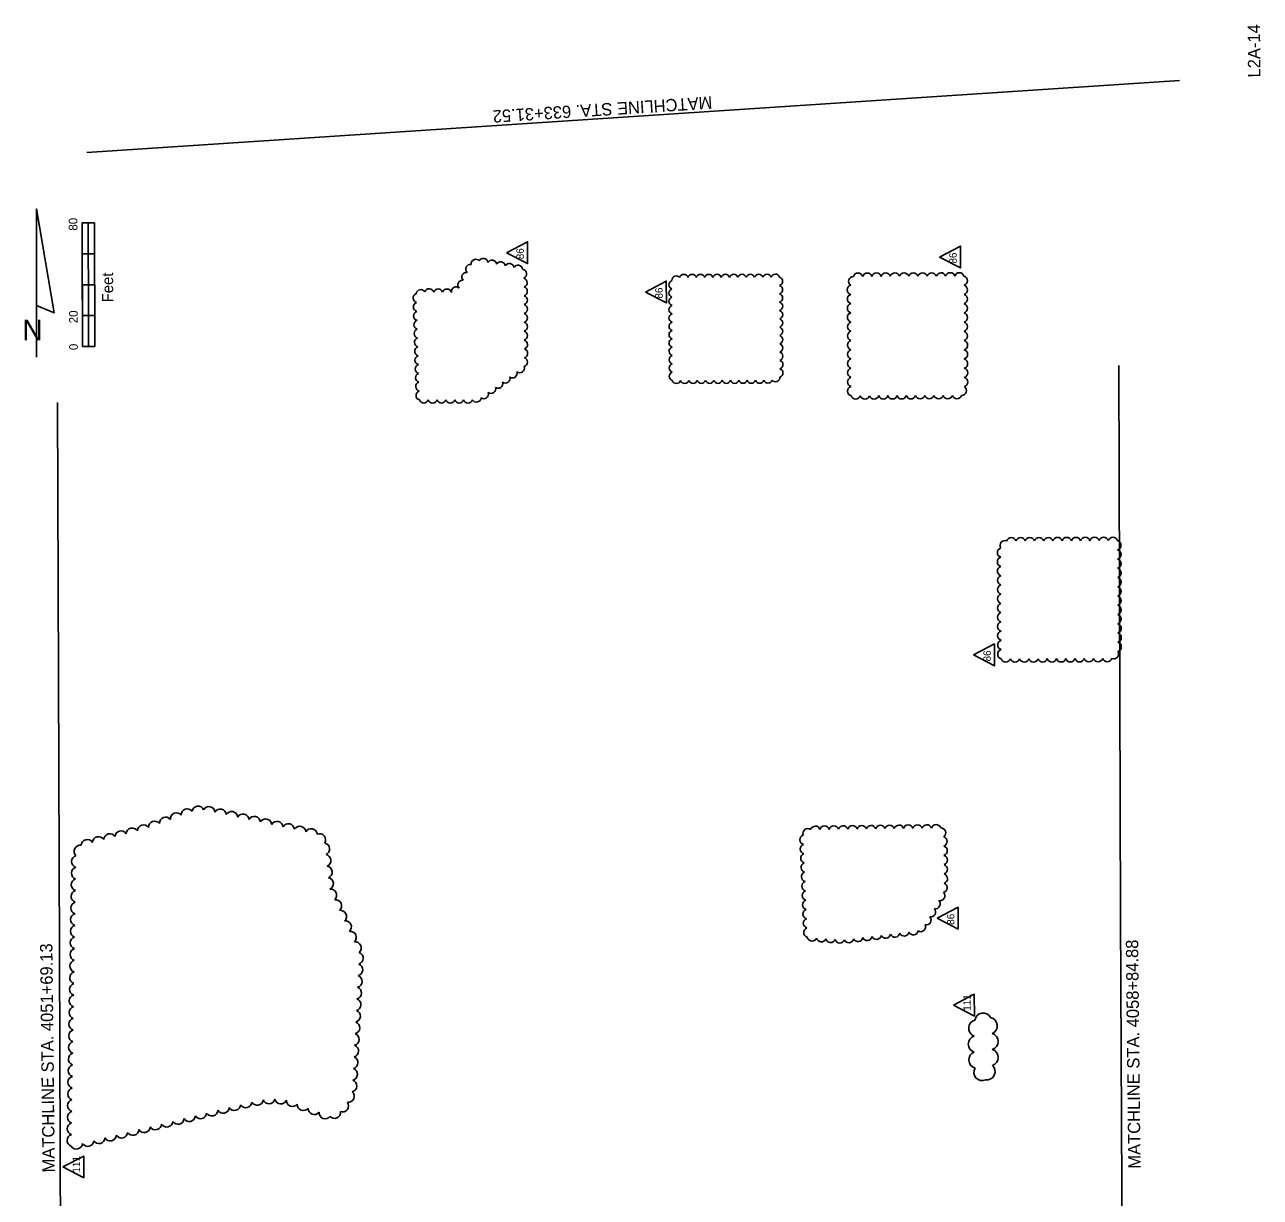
# Model space of a CAD drawing. Extents: x 928735 to 929560, y 637957 to 639219.
# Drawn here: x 928735 to 929535, y 638460 to 639219 of the extents above; entities that cross this region are included whole.
import ezdxf

# ---------------------------------------------------------------- set-up
doc = ezdxf.new("R2010")
doc.units = 0
for name, color, linetype in [('Cloud_dp', 7, 'Continuous'), ('MatchLines_dp', 7, 'Continuous'), ('NorthArw_dp', 7, 'Continuous'), ('Scale_dp', 7, 'Continuous'), ('TextShtNo', 7, 'Continuous')]:
    doc.layers.add(name, color=color, linetype=linetype)

msp = doc.modelspace()

# ---------------------------------------------------------------- linework, layer by layer
at = {"layer": 'Cloud_dp'}
for points in [[(929047.1, 639071.19), (929060.69, 639064.19), (929060.64, 639078.28)], [(929327.44, 639068.38), (929341.03, 639061.39), (929340.98, 639075.47)], [(929136.99, 639045.72), (929150.58, 639038.73), (929150.53, 639052.81)], [(929349.53, 638810.78), (929363.11, 638803.78), (929363.07, 638817.87)], [(929325.95, 638640.25), (929339.53, 638633.26), (929339.49, 638647.34)], [(929336.48, 638583.91), (929350.06, 638576.91), (929350.02, 638591)], [(928759.68, 638479.2), (928773.27, 638472.2), (928773.22, 638486.29)]]:
    msp.add_lwpolyline(points, close=True, dxfattribs=at)
for centre, radius, start, end in [((929027.13, 639063.94), 3.01, 41.87422, 186.87422), ((929032.01, 639064.5), 3.01, 6.44158, 151.44158), ((929037.63, 639063.4), 3.01, 6.44158, 151.44158), ((929043.26, 639062.31), 3.01, 6.44158, 151.44158), ((929021.11, 639055.48), 3.01, 80.96807, 225.96807), ((929023.67, 639060.61), 3.01, 80.96807, 225.96807), ((929048.88, 639061.21), 3.01, 6.44158, 151.44158), ((929054.51, 639060.11), 3, 6.44158, 151.44158), ((929057.03, 639057.47), 3.01, 296.04486, 81.04486), ((929161.87, 639054.29), 2.83, 17.69643, 162.69643), ((929167.26, 639054.31), 2.83, 17.69643, 162.69643), ((929172.66, 639054.33), 2.83, 17.69643, 162.69643), ((929178.05, 639054.35), 2.83, 17.69643, 162.69643), ((929183.44, 639054.37), 2.83, 17.69643, 162.69643), ((929188.83, 639054.39), 2.83, 17.69643, 162.69643), ((929194.22, 639054.4), 2.83, 17.69643, 162.69643), ((929199.61, 639054.42), 2.83, 17.69643, 162.69643), ((929205, 639054.44), 2.83, 17.69643, 162.69643), ((929210.39, 639054.46), 2.83, 17.69643, 162.69643), ((929215.78, 639054.48), 2.83, 17.69643, 162.69643), ((929221.17, 639054.5), 2.83, 17.69643, 162.69643), ((929274.73, 639054.9), 3.13, 17.69643, 162.69643), ((929280.69, 639054.92), 3.13, 17.69643, 162.69643), ((929286.66, 639054.94), 3.13, 17.69643, 162.69643), ((929292.62, 639054.96), 3.13, 17.69643, 162.69643), ((929298.59, 639054.98), 3.13, 17.69643, 162.69643), ((929304.55, 639055), 3.13, 17.69643, 162.69643), ((929310.52, 639055.02), 3.13, 17.69643, 162.69643), ((929316.48, 639055.04), 3.13, 17.69643, 162.69643), ((929322.44, 639055.06), 3.13, 17.69643, 162.69643), ((929328.41, 639055.08), 3.13, 17.69643, 162.69643), ((929334.37, 639055.1), 3.13, 17.69643, 162.69643), ((929340.34, 639055.12), 3.13, 17.69643, 162.69643), ((929014.35, 639046.05), 3.01, 45.32878, 190.32878), ((929018.55, 639050.35), 3.01, 80.96807, 225.96807), ((929057.46, 639051.9), 3.01, 287.80104, 72.80104), ((929057.49, 639046.17), 3.01, 287.80104, 72.80104), ((929155.03, 639050.45), 2.83, 107.69643, 252.69643), ((929156.99, 639053.35), 2.82, 39.1821, 184.1821), ((929223.03, 639052.66), 2.83, 287.69643, 72.69643), ((929223.04, 639047.27), 2.83, 287.69643, 72.69643), ((929270.89, 639047.17), 3.13, 107.69643, 252.69643), ((929271.73, 639052.7), 3.12, 89.88872, 234.88872), ((929342.39, 639053.09), 3.13, 287.69643, 72.69643), ((929342.41, 639047.12), 3.13, 287.69643, 72.69643), ((928989.57, 639041.78), 3.01, 109.1948, 254.1948), ((928991.58, 639044.31), 3, 29.17471, 174.17471), ((928997.05, 639044.83), 3.01, 16.63437, 161.63437), ((929002.78, 639044.74), 3.01, 16.63437, 161.63437), ((929008.51, 639044.65), 3.01, 16.63437, 161.63437), ((929057.52, 639040.44), 3.01, 287.80104, 72.80104), ((929155.05, 639045.06), 2.83, 107.69643, 252.69643), ((929155.07, 639039.67), 2.83, 107.69643, 252.69643), ((929223.06, 639041.88), 2.83, 287.69643, 72.69643), ((929270.91, 639041.2), 3.13, 107.69643, 252.69643), ((929342.43, 639041.16), 3.13, 287.69643, 72.69643), ((928989.74, 639036.05), 3.01, 109.1948, 254.1948), ((928989.91, 639030.32), 3.01, 109.1948, 254.1948), ((929057.55, 639034.7), 3.01, 287.80104, 72.80104), ((929155.08, 639034.28), 2.83, 107.69643, 252.69643), ((929223.08, 639036.49), 2.83, 287.69643, 72.69643), ((929223.1, 639031.09), 2.83, 287.69643, 72.69643), ((929270.93, 639035.24), 3.13, 107.69643, 252.69643), ((929342.45, 639035.19), 3.13, 287.69643, 72.69643), ((928990.08, 639024.59), 3.01, 109.1948, 254.1948), ((929057.58, 639028.97), 3.01, 287.80104, 72.80104), ((929057.61, 639023.24), 3.01, 287.80104, 72.80104), ((929155.1, 639028.89), 2.83, 107.69643, 252.69643), ((929155.12, 639023.5), 2.83, 107.69643, 252.69643), ((929223.12, 639025.7), 2.83, 287.69643, 72.69643), ((929270.95, 639029.27), 3.13, 107.69643, 252.69643), ((929270.97, 639023.31), 3.13, 107.69643, 252.69643), ((929342.47, 639029.23), 3.13, 287.69643, 72.69643), ((929342.49, 639023.26), 3.13, 287.69643, 72.69643), ((928990.25, 639018.86), 3.01, 109.1948, 254.1948), ((929057.64, 639017.51), 3.01, 287.80104, 72.80104), ((929155.14, 639018.11), 2.83, 107.69643, 252.69643), ((929223.14, 639020.31), 2.83, 287.69643, 72.69643), ((929223.15, 639014.92), 2.83, 287.69643, 72.69643), ((929270.99, 639017.34), 3.13, 107.69643, 252.69643), ((929342.51, 639017.3), 3.13, 287.69643, 72.69643), ((928990.42, 639013.13), 3.01, 109.1948, 254.1948), ((928990.59, 639007.4), 3.01, 109.1948, 254.1948), ((929057.67, 639011.77), 3.01, 287.80104, 72.80104), ((929057.7, 639006.04), 3.01, 287.80104, 72.80104), ((929155.16, 639012.72), 2.83, 107.69643, 252.69643), ((929155.18, 639007.32), 2.83, 107.69643, 252.69643), ((929223.17, 639009.53), 2.83, 287.69643, 72.69643), ((929271.01, 639011.38), 3.13, 107.69643, 252.69643), ((929342.53, 639011.33), 3.13, 287.69643, 72.69643), ((928990.76, 639001.67), 3.01, 109.1948, 254.1948), ((929057.63, 639000.34), 3.01, 285.75263, 70.75263), ((929155.2, 639001.93), 2.83, 107.69643, 252.69643), ((929223.19, 639004.14), 2.83, 287.69643, 72.69643), ((929223.21, 638998.75), 2.83, 287.69643, 72.69643), ((929271.03, 639005.41), 3.13, 107.69643, 252.69643), ((929271.05, 638999.45), 3.13, 107.69643, 252.69643), ((929342.55, 639005.37), 3.13, 287.69643, 72.69643), ((929342.57, 638999.4), 3.13, 287.69643, 72.69643), ((928990.93, 638995.94), 3.01, 109.1948, 254.1948), ((928991.1, 638990.21), 3.01, 109.1948, 254.1948), ((929050.95, 638993.13), 3.01, 233.44773, 18.44773), ((929055.59, 638996.5), 3, 233.44773, 18.44773), ((929155.21, 638996.54), 2.83, 107.69643, 252.69643), ((929155.23, 638991.15), 2.83, 107.69643, 252.69643), ((929223.23, 638993.36), 2.83, 287.69643, 72.69643), ((929271.07, 638993.49), 3.13, 107.69643, 252.69643), ((929342.59, 638993.44), 3.13, 287.69643, 72.69643), ((928991.27, 638984.48), 3.01, 109.1948, 254.1948), ((929041.67, 638986.4), 3.01, 233.44773, 18.44773), ((929046.31, 638989.77), 3.01, 233.44773, 18.44773), ((929157.08, 638989.31), 2.83, 197.69643, 342.69643), ((929162.48, 638989.33), 2.83, 197.69643, 342.69643), ((929167.87, 638989.35), 2.83, 197.69643, 342.69643), ((929173.26, 638989.37), 2.83, 197.69643, 342.69643), ((929178.65, 638989.39), 2.83, 197.69643, 342.69643), ((929184.04, 638989.41), 2.83, 197.69643, 342.69643), ((929189.43, 638989.42), 2.83, 197.69643, 342.69643), ((929194.82, 638989.44), 2.83, 197.69643, 342.69643), ((929200.21, 638989.46), 2.83, 197.69643, 342.69643), ((929205.6, 638989.48), 2.83, 197.69643, 342.69643), ((929210.99, 638989.5), 2.83, 197.69643, 342.69643), ((929216.38, 638989.52), 2.83, 197.69643, 342.69643), ((929221.27, 638990.46), 2.82, 219.1821, 4.1821), ((929271.09, 638987.52), 3.13, 107.69643, 252.69643), ((929271.11, 638981.56), 3.13, 107.69643, 252.69643), ((929342.61, 638987.47), 3.13, 287.69643, 72.69643), ((928991.44, 638978.75), 3.01, 109.1948, 254.1948), ((929027.6, 638977.5), 3.01, 210.44534, 355.44534), ((929032.39, 638979.67), 3.01, 233.44773, 18.44773), ((929037.03, 638983.04), 3.01, 233.44773, 18.44773), ((929273.16, 638979.52), 3.13, 197.69643, 342.69643), ((929279.13, 638979.54), 3.13, 197.69643, 342.69643), ((929285.09, 638979.56), 3.13, 197.69643, 342.69643), ((929291.06, 638979.58), 3.13, 197.69643, 342.69643), ((929297.02, 638979.6), 3.13, 197.69643, 342.69643), ((929302.99, 638979.62), 3.13, 197.69643, 342.69643), ((929308.95, 638979.64), 3.13, 197.69643, 342.69643), ((929314.92, 638979.66), 3.13, 197.69643, 342.69643), ((929320.88, 638979.68), 3.13, 197.69643, 342.69643), ((929326.85, 638979.7), 3.13, 197.69643, 342.69643), ((929332.81, 638979.72), 3.13, 197.69643, 342.69643), ((929338.78, 638979.75), 3.13, 197.69643, 342.69643), ((929341.77, 638981.94), 3.12, 269.88872, 54.88872), ((928993.48, 638976.77), 3.01, 197.69643, 342.69643), ((928999.22, 638976.79), 3.01, 197.69643, 342.69643), ((929004.95, 638976.81), 3.01, 197.69643, 342.69643), ((929010.68, 638976.83), 3.01, 197.69643, 342.69643), ((929016.41, 638976.85), 3.01, 197.69643, 342.69643), ((929022.14, 638976.87), 3.01, 197.69643, 342.69643), ((929369.78, 638881.66), 3.13, 66.77308, 211.77308), ((929374.01, 638883.61), 3.14, 17.69643, 162.69643), ((929379.99, 638883.63), 3.14, 17.69643, 162.69643), ((929385.97, 638883.65), 3.14, 17.69643, 162.69643), ((929391.95, 638883.67), 3.14, 17.69643, 162.69643), ((929397.93, 638883.69), 3.14, 17.69643, 162.69643), ((929403.91, 638883.71), 3.14, 17.69643, 162.69643), ((929409.9, 638883.73), 3.14, 17.69643, 162.69643), ((929415.88, 638883.75), 3.14, 17.69643, 162.69643), ((929421.86, 638883.77), 3.14, 17.69643, 162.69643), ((929427.84, 638883.79), 3.14, 17.69643, 162.69643), ((929433.82, 638883.81), 3.14, 17.69643, 162.69643), ((929439.8, 638883.83), 3.14, 17.69643, 162.69643), ((929441.85, 638881.79), 3.14, 287.69643, 72.69643), ((929368.07, 638877.02), 3.14, 107.69643, 252.69643), ((929368.09, 638871.04), 3.14, 107.69643, 252.69643), ((929441.87, 638875.81), 3.14, 287.69643, 72.69643), ((929441.89, 638869.83), 3.14, 287.69643, 72.69643), ((929368.11, 638865.06), 3.14, 107.69643, 252.69643), ((929441.92, 638863.85), 3.14, 287.69643, 72.69643), ((929368.13, 638859.08), 3.14, 107.69643, 252.69643), ((929441.94, 638857.87), 3.14, 287.69643, 72.69643), ((929368.15, 638853.1), 3.14, 107.69643, 252.69643), ((929368.17, 638847.12), 3.14, 107.69643, 252.69643), ((929441.96, 638851.89), 3.14, 287.69643, 72.69643), ((929441.98, 638845.91), 3.14, 287.69643, 72.69643), ((929368.19, 638841.14), 3.14, 107.69643, 252.69643), ((929442, 638839.93), 3.14, 287.69643, 72.69643), ((929368.21, 638835.16), 3.14, 107.69643, 252.69643), ((929442.02, 638833.95), 3.14, 287.69643, 72.69643), ((929368.23, 638829.18), 3.14, 107.69643, 252.69643), ((929368.26, 638823.2), 3.14, 107.69643, 252.69643), ((929442.04, 638827.97), 3.14, 287.69643, 72.69643), ((929442.06, 638821.99), 3.14, 287.69643, 72.69643), ((929368.28, 638817.22), 3.14, 107.69643, 252.69643), ((929442.08, 638816.01), 3.14, 287.69643, 72.69643), ((929368.3, 638811.24), 3.14, 107.69643, 252.69643), ((929436.14, 638809.42), 3.14, 197.69643, 342.69643), ((929440.37, 638811.37), 3.13, 246.77308, 31.77308), ((929370.35, 638809.2), 3.14, 197.69643, 342.69643), ((929376.33, 638809.22), 3.14, 197.69643, 342.69643), ((929382.31, 638809.24), 3.14, 197.69643, 342.69643), ((929388.29, 638809.26), 3.14, 197.69643, 342.69643), ((929394.27, 638809.28), 3.14, 197.69643, 342.69643), ((929400.25, 638809.3), 3.14, 197.69643, 342.69643), ((929406.24, 638809.32), 3.14, 197.69643, 342.69643), ((929412.22, 638809.34), 3.14, 197.69643, 342.69643), ((929418.2, 638809.36), 3.14, 197.69643, 342.69643), ((929424.18, 638809.38), 3.14, 197.69643, 342.69643), ((929430.16, 638809.4), 3.14, 197.69643, 342.69643), ((928847.29, 638708.9), 3.95, 24.77078, 169.77078), ((928854.3, 638708.6), 3.95, 5.31461, 150.31461), ((928826.23, 638701.84), 3.95, 38.20479, 183.20479), ((928833.27, 638704.5), 3.95, 38.20479, 183.20479), ((928840.31, 638707.16), 3.95, 38.20479, 183.20479), ((928861.66, 638707.01), 3.95, 5.31461, 150.31461), ((928869.01, 638705.42), 3.95, 5.31461, 150.31461), ((928876.37, 638703.83), 3.95, 5.31461, 150.31461), ((928883.72, 638702.24), 3.95, 5.31461, 150.31461), ((928891.08, 638700.65), 3.95, 5.31461, 150.31461), ((928797.4, 638692.87), 3.95, 31.87512, 176.87512), ((928804.69, 638694.73), 3.95, 31.87512, 176.87512), ((928811.98, 638696.75), 3.95, 33.99958, 178.99958), ((928819.19, 638699.18), 3.95, 38.20479, 183.20479), ((928898.44, 638699.07), 3.95, 5.31461, 150.31461), ((928905.79, 638697.48), 3.95, 5.31461, 150.31461), ((928913.15, 638695.89), 3.95, 5.31461, 150.31461), ((928920.5, 638694.3), 3.95, 5.31461, 150.31461), ((929242.15, 638695.13), 3.15, 53.92896, 198.92896), ((929247.02, 638696.77), 3.16, 18.19349, 163.19349), ((929253.04, 638696.84), 3.16, 18.19349, 163.19349), ((929259.06, 638696.91), 3.16, 18.19349, 163.19349), ((929265.08, 638696.98), 3.16, 18.19349, 163.19349), ((929271.1, 638697.06), 3.16, 18.19349, 163.19349), ((929277.12, 638697.13), 3.16, 18.19349, 163.19349), ((929283.13, 638697.2), 3.16, 18.19349, 163.19349), ((929289.15, 638697.28), 3.16, 18.19349, 163.19349), ((929295.17, 638697.35), 3.16, 18.19349, 163.19349), ((929301.19, 638697.42), 3.16, 18.19349, 163.19349), ((929307.21, 638697.49), 3.16, 18.19349, 163.19349), ((929313.23, 638697.57), 3.16, 18.19349, 163.19349), ((929319.24, 638697.64), 3.16, 18.19349, 163.19349), ((929325.26, 638697.71), 3.16, 18.19349, 163.19349), ((929328.35, 638695.55), 3.15, 306.63247, 91.63247), ((928775.53, 638687.26), 3.95, 31.87512, 176.87512), ((928782.82, 638689.13), 3.95, 31.87512, 176.87512), ((928790.11, 638691), 3.95, 31.87512, 176.87512), ((928925.98, 638691.04), 3.95, 328.17052, 113.17052), ((928928.57, 638685.09), 3.95, 293.74766, 78.74766), ((929240.23, 638691.14), 3.16, 109.81544, 254.81544), ((929329.31, 638690), 3.16, 288.01668, 73.01668), ((928769.33, 638676.97), 3.95, 106.56514, 251.56514), ((928770.95, 638683.58), 3.95, 80.7548, 225.7548), ((928929.38, 638677.61), 3.95, 293.74766, 78.74766), ((929240.47, 638685.12), 3.16, 109.81544, 254.81544), ((929240.72, 638679.11), 3.16, 109.81544, 254.81544), ((929329.37, 638683.98), 3.16, 288.01668, 73.01668), ((929329.42, 638677.96), 3.16, 288.01668, 73.01668), ((928769.2, 638669.45), 3.95, 106.56514, 251.56514), ((928930.2, 638670.13), 3.95, 293.74766, 78.74766), ((929240.96, 638673.09), 3.16, 109.81544, 254.81544), ((929329.47, 638671.94), 3.16, 288.01668, 73.01668), ((928769.08, 638661.93), 3.95, 106.56514, 251.56514), ((928931.02, 638662.65), 3.95, 293.74766, 78.74766), ((929241.2, 638667.08), 3.16, 109.81544, 254.81544), ((929329.53, 638665.92), 3.16, 288.01668, 73.01668), ((928768.96, 638654.4), 3.95, 106.56514, 251.56514), ((928933.11, 638655.12), 3.95, 312.21207, 97.21207), ((929241.45, 638661.07), 3.16, 109.81544, 254.81544), ((929241.69, 638655.05), 3.16, 109.81544, 254.81544), ((929327.76, 638654.77), 3.16, 257.91481, 42.91481), ((929329.34, 638659.99), 3.16, 283.34081, 68.34081), ((928768.84, 638646.88), 3.95, 106.56514, 251.56514), ((928936.28, 638648.29), 3.95, 312.56023, 97.56023), ((929241.93, 638649.04), 3.16, 109.81544, 254.81544), ((929324.79, 638649.54), 3.16, 257.91481, 42.91481), ((928768.71, 638639.35), 3.95, 106.56514, 251.56514), ((928939.46, 638641.47), 3.95, 312.56023, 97.56023), ((929242.18, 638643.02), 3.16, 109.81544, 254.81544), ((929318.84, 638639.07), 3.16, 257.91481, 42.91481), ((929321.81, 638644.3), 3.16, 257.91481, 42.91481), ((928768.59, 638631.83), 3.95, 106.56514, 251.56514), ((928942.65, 638634.66), 3.95, 312.56023, 97.56023), ((929242.42, 638637.01), 3.16, 109.81544, 254.81544), ((929242.66, 638631), 3.16, 109.81544, 254.81544), ((929315.29, 638634.71), 3.16, 238.69803, 23.69803), ((928768.47, 638624.31), 3.95, 106.56514, 251.56514), ((928945.84, 638627.84), 3.95, 312.56023, 97.56023), ((928949.03, 638621.02), 3.94, 312.56023, 97.56023), ((929244.91, 638628.65), 3.16, 192.7669, 337.7669), ((929250.91, 638628.15), 3.16, 192.7669, 337.7669), ((929256.91, 638627.66), 3.16, 192.7669, 337.7669), ((929262.87, 638627.31), 3.15, 195.57497, 340.57497), ((929268.72, 638627.56), 3.16, 204.36858, 349.36858), ((929274.7, 638628.28), 3.16, 204.36858, 349.36858), ((929280.67, 638629), 3.16, 204.36858, 349.36858), ((929286.65, 638629.72), 3.16, 204.36858, 349.36858), ((929292.62, 638630.44), 3.16, 204.36858, 349.36858), ((929298.6, 638631.16), 3.16, 204.36858, 349.36858), ((929304.58, 638631.88), 3.16, 204.36858, 349.36858), ((929310.55, 638632.6), 3.16, 204.36858, 349.36858), ((928768.34, 638616.78), 3.95, 106.56514, 251.56514), ((928950.34, 638614.41), 3.95, 284.91772, 69.91772), ((928768.22, 638609.26), 3.95, 106.56514, 251.56514), ((928949.98, 638606.9), 3.95, 284.56948, 69.56948), ((928768.1, 638601.73), 3.95, 106.56514, 251.56514), ((928949.59, 638599.38), 3.95, 284.56948, 69.56948), ((928767.98, 638594.21), 3.95, 106.56514, 251.56514), ((928949.21, 638591.87), 3.95, 284.56948, 69.56948), ((928767.85, 638586.68), 3.95, 106.56514, 251.56514), ((928948.82, 638584.35), 3.95, 284.56948, 69.56948), ((928767.73, 638579.16), 3.95, 106.56514, 251.56514), ((928948.44, 638576.84), 3.95, 284.56948, 69.56948), ((929355.74, 638573.51), 5.42, 26.70049, 171.70049), ((928767.61, 638571.64), 3.95, 106.56514, 251.56514), ((928948.05, 638569.32), 3.95, 284.56948, 69.56948), ((929351.77, 638569.05), 5.42, 104.8481, 249.8481), ((929359.48, 638570.63), 5.42, 293.26742, 78.26742), ((928767.48, 638564.11), 3.95, 106.56514, 251.56514), ((928947.67, 638561.81), 3.95, 284.56948, 69.56948), ((929351.55, 638558.79), 5.42, 107.76365, 252.76365), ((929360.01, 638560.47), 5.42, 287.77464, 72.77464), ((928767.24, 638549.06), 3.95, 106.56514, 251.56514), ((928767.36, 638556.59), 3.95, 106.56514, 251.56514), ((928947.28, 638554.29), 3.95, 284.56948, 69.56948), ((929351.84, 638548.53), 5.42, 110.37062, 255.37062), ((929360.05, 638550.13), 5.42, 287.69643, 72.69643), ((928767.12, 638541.54), 3.95, 106.56514, 251.56514), ((928946.9, 638546.78), 3.95, 284.56948, 69.56948), ((929358.05, 638540.95), 5.42, 262.68914, 47.68914), ((928766.99, 638534.01), 3.95, 106.56514, 251.56514), ((928946.51, 638539.26), 3.95, 284.56948, 69.56948), ((929355.13, 638540.51), 5.42, 149.33139, 294.33139), ((928766.87, 638526.49), 3.95, 106.56514, 251.56514), ((928946.13, 638531.75), 3.95, 284.56948, 69.56948), ((928766.75, 638518.97), 3.95, 106.56514, 251.56514), ((928878.15, 638521.53), 3.95, 211.25306, 356.25306), ((928885.58, 638523.11), 3.95, 207.78298, 352.78298), ((928893.17, 638524.04), 3.94, 201.18897, 346.18897), ((928900.84, 638524.02), 3.95, 193.40806, 338.40806), ((928908.44, 638522.35), 3.95, 176.84652, 321.84652), ((928940.83, 638518.76), 3.95, 250.88199, 35.88199), ((928944.49, 638524.99), 3.95, 263.20516, 48.20516), ((928766.63, 638511.44), 3.95, 106.56514, 251.56514), ((928848.91, 638514.38), 3.95, 211.25306, 356.25306), ((928856.22, 638516.17), 3.95, 211.25306, 356.25306), ((928863.53, 638517.95), 3.95, 211.25306, 356.25306), ((928870.84, 638519.74), 3.95, 211.25306, 356.25306), ((928915.49, 638519.69), 3.95, 176.84652, 321.84652), ((928922.53, 638517.04), 3.95, 176.84652, 321.84652), ((928929.57, 638514.39), 3.95, 176.84652, 321.84652), ((928935.62, 638514.57), 3.95, 221.66238, 6.66238), ((928766.5, 638503.92), 3.95, 106.56514, 251.56514), ((928812.36, 638505.43), 3.95, 211.25306, 356.25306), ((928819.67, 638507.22), 3.95, 211.25306, 356.25306), ((928826.98, 638509.01), 3.95, 211.25306, 356.25306), ((928834.29, 638510.8), 3.95, 211.25306, 356.25306), ((928841.6, 638512.59), 3.95, 211.25306, 356.25306), ((928766.38, 638496.39), 3.95, 106.56514, 251.56514), ((928783.12, 638498.27), 3.95, 211.25306, 356.25306), ((928790.43, 638500.06), 3.95, 211.25306, 356.25306), ((928797.74, 638501.85), 3.95, 211.25306, 356.25306), ((928805.05, 638503.64), 3.95, 211.25306, 356.25306), ((928768.5, 638494.7), 3.95, 211.25306, 356.25306), ((928775.81, 638496.49), 3.95, 211.25306, 356.25306)]:
    msp.add_arc(centre, radius, start, end, dxfattribs=at)
at = {"layer": 'MatchLines_dp'}
for points in [[(929482.89, 639182.75), (929099.75, 639157.52), (928775.28, 639136.16)], [(929443.52, 638998.1), (929444.75, 638641.91), (929446.91, 638200.47)], [(928756.17, 638974.21), (928757.64, 638618.14), (928759.14, 638176.75)]]:
    msp.add_lwpolyline(points, dxfattribs=at)
at = {"layer": 'NorthArw_dp'}
msp.add_line((928742.66, 639003.51), (928742.66, 639099.51), dxfattribs=at)
msp.add_lwpolyline([(928742.66, 639037.11), (928742.66, 639099.51), (928754.18, 639032.31)], close=True, dxfattribs=at)
at = {"layer": 'Scale_dp'}
for p, q in [((928780.14, 639090.49), (928772.14, 639090.47)), ((928772.14, 639090.47), (928772.42, 639010.47)), ((928780.42, 639010.49), (928780.14, 639090.49)), ((928772.42, 639010.47), (928780.42, 639010.49))]:
    msp.add_line(p, q, dxfattribs=at)
for points in [[(928776.21, 639070.48), (928772.21, 639070.47), (928772.14, 639090.47), (928776.14, 639090.48)], [(928780.28, 639050.49), (928776.28, 639050.48), (928776.21, 639070.48), (928780.21, 639070.49)], [(928776.35, 639030.48), (928772.35, 639030.47), (928772.28, 639050.47), (928776.28, 639050.48)], [(928780.42, 639010.49), (928776.42, 639010.48), (928776.35, 639030.48), (928780.35, 639030.49)]]:
    msp.add_lwpolyline(points, close=True, dxfattribs=at)

# ---------------------------------------------------------------- texts
at = {"layer": 'Cloud_dp'}
for s, p in [('86', (929058.27, 639066.96)), ('86', (929338.61, 639064.16)), ('86', (929148.16, 639041.5)), ('86', (929360.69, 638806.55)), ('86', (929337.11, 638636.03)), ('111', (929347.64, 638580.32)), ('111', (928770.84, 638475.61))]:
    msp.add_text(s, height=4.8, rotation=90.19643, dxfattribs=at).set_placement(p)
at = {"layer": 'MatchLines_dp'}
for s, rotation, p in [('MATCHLINE STA. 633+31.52', 183.67051, (929180.03, 639172.45)), ('MATCHLINE STA. 4058+84.88', 90.62715, (929457.73, 638478.12)), ('MATCHLINE STA. 4051+69.13', 90.62715, (928754.54, 638475.68))]:
    msp.add_text(s, height=8, rotation=rotation, dxfattribs=at).set_placement(p)
at = {"layer": 'NorthArw_dp'}
msp.add_text('N', height=13.43, dxfattribs=at).set_placement((928733.54, 639014.38))
at = {"layer": 'Scale_dp'}
for s, height, p in [('80', 5.6, (928769.16, 639085.47)), ('Feet', 7.2, (928792.32, 639039.08)), ('20', 5.6, (928769.37, 639025.49)), ('0', 5.6, (928769.43, 639008.13))]:
    msp.add_text(s, height=height, rotation=90.19643, dxfattribs=at).set_placement(p)
at = {"layer": 'TextShtNo'}
msp.add_text('L2A-14', height=8, rotation=90.19643, dxfattribs=at).set_placement((929535.22, 639184.64))

doc.saveas('drawing.dxf')
